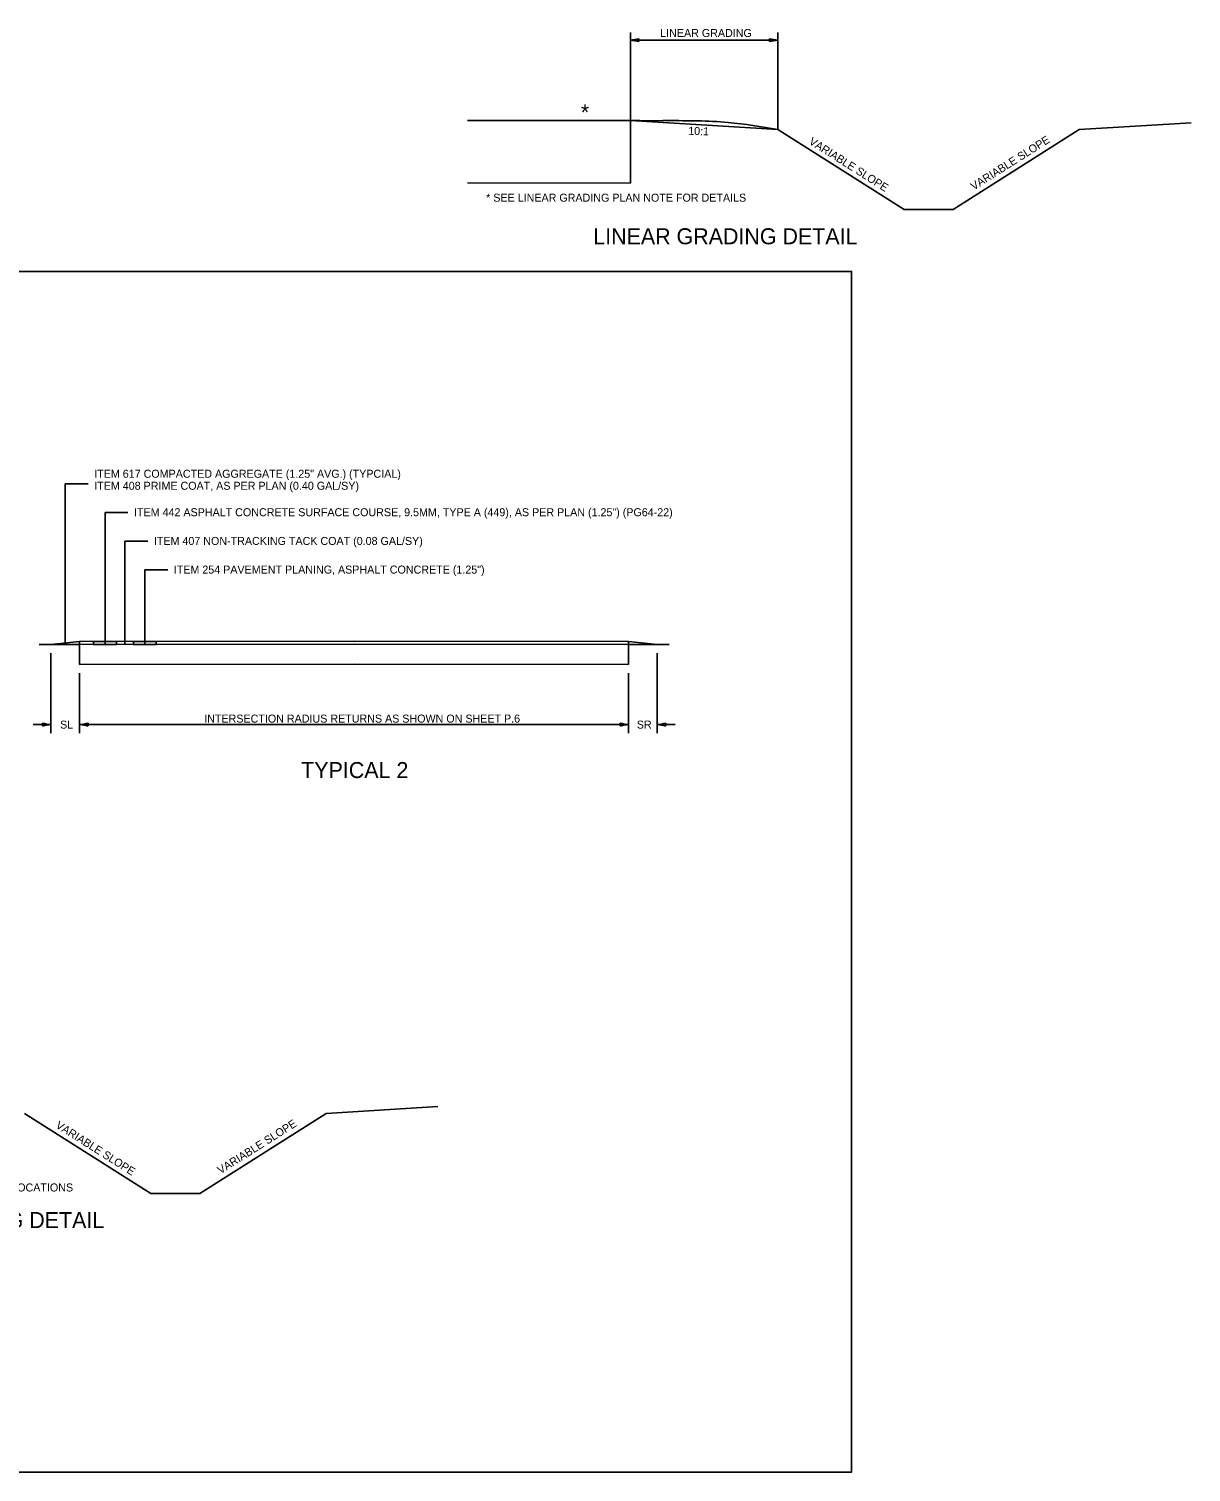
# Model space of a CAD drawing. Extents: x 12069 to 12219, y 28137 to 28231.
# Drawn here: x 12085.56 to 12105.88, y 28179.53 to 28204.77 of the extents above; entities that cross this region are included whole.
import ezdxf

# ---------------------------------------------------------------- set-up
doc = ezdxf.new("R2010")
doc.units = 0
doc.layers.add('SC_Scratch1', color=7, linetype='Continuous')
doc.layers.add('SH_Data', color=7, linetype='Continuous')

msp = doc.modelspace()

# ---------------------------------------------------------------- linework, layer by layer
at = {"layer": 'SC_Scratch1'}
msp.add_lwpolyline([(12069.445, 28200.534), (12099.945, 28200.534), (12099.945, 28179.534), (12069.445, 28179.534)], close=True, dxfattribs=at)
at = {"layer": 'SH_Data'}
for p, q in [((12096.078, 28203.247), (12096.078, 28204.711)), ((12096.078, 28204.577), (12098.656, 28204.577)), ((12096.219, 28204.577), (12096.228, 28204.602)), ((12096.228, 28204.552), (12096.219, 28204.577)), ((12098.506, 28204.602), (12098.515, 28204.577)), ((12098.515, 28204.577), (12098.506, 28204.552)), ((12098.656, 28203.012), (12098.656, 28204.711)), ((12096.078, 28203.169), (12096.078, 28203.325)), ((12093.231, 28203.173), (12096.078, 28203.169)), ((12098.656, 28203.012), (12096.078, 28203.169)), ((12096.078, 28202.075), (12096.078, 28203.169)), ((12103.927, 28203.012), (12105.882, 28203.132)), ((12098.656, 28203.012), (12100.864, 28201.614)), ((12103.927, 28203.012), (12101.719, 28201.614)), ((12093.229, 28202.079), (12096.078, 28202.075)), ((12100.864, 28201.614), (12101.719, 28201.614)), ((12086.197, 28194.033), (12086.197, 28196.819)), ((12086.197, 28196.819), (12086.597, 28196.819)), ((12086.892, 28194.008), (12086.892, 28196.318)), ((12086.892, 28196.318), (12087.292, 28196.318)), ((12087.24, 28194.009), (12087.24, 28195.817)), ((12087.24, 28195.817), (12087.64, 28195.817)), ((12087.588, 28194.009), (12087.588, 28195.315)), ((12087.588, 28195.315), (12087.988, 28195.315)), ((12086.447, 28194.008), (12085.739, 28194.008)), ((12085.947, 28194.008), (12086.447, 28194.058)), ((12091.247, 28194.065), (12086.447, 28194.058)), ((12086.447, 28194.008), (12086.447, 28194.058)), ((12091.247, 28194.015), (12086.447, 28194.008)), ((12086.447, 28193.958), (12086.447, 28194.008)), ((12086.692, 28194.058), (12087.092, 28194.059)), ((12086.692, 28194.008), (12086.692, 28194.058)), ((12087.092, 28194.009), (12086.692, 28194.008)), ((12087.092, 28194.059), (12087.092, 28194.009)), ((12087.388, 28194.059), (12087.788, 28194.06)), ((12087.388, 28194.009), (12087.388, 28194.059)), ((12087.788, 28194.01), (12087.388, 28194.009)), ((12087.788, 28194.06), (12087.788, 28194.01)), ((12091.247, 28194.065), (12096.047, 28194.058)), ((12091.247, 28194.015), (12096.047, 28194.008)), ((12096.047, 28194.008), (12096.047, 28194.058)), ((12096.547, 28194.008), (12096.047, 28194.058)), ((12096.047, 28193.958), (12096.047, 28194.008)), ((12096.047, 28194.008), (12096.755, 28194.008)), ((12085.947, 28193.858), (12085.947, 28192.458)), ((12086.447, 28193.658), (12086.447, 28193.958)), ((12096.047, 28193.658), (12096.047, 28193.958)), ((12096.547, 28193.858), (12096.547, 28192.458)), ((12091.247, 28193.665), (12086.447, 28193.658)), ((12086.447, 28193.508), (12086.447, 28192.458)), ((12091.247, 28193.665), (12096.047, 28193.658)), ((12096.047, 28193.508), (12096.047, 28192.458)), ((12085.947, 28192.608), (12085.634, 28192.608)), ((12085.797, 28192.633), (12085.805, 28192.608)), ((12085.805, 28192.608), (12085.797, 28192.583)), ((12086.447, 28192.608), (12096.047, 28192.608)), ((12086.589, 28192.608), (12086.597, 28192.633)), ((12086.597, 28192.583), (12086.589, 28192.608)), ((12095.897, 28192.633), (12095.905, 28192.608)), ((12095.905, 28192.608), (12095.897, 28192.583)), ((12096.547, 28192.608), (12096.86, 28192.608)), ((12096.697, 28192.633), (12096.689, 28192.608)), ((12096.689, 28192.608), (12096.697, 28192.583)), ((12090.757, 28185.807), (12092.712, 28185.927)), ((12085.486, 28185.807), (12087.694, 28184.409)), ((12090.757, 28185.807), (12088.549, 28184.409)), ((12087.694, 28184.409), (12088.549, 28184.409))]:
    msp.add_line(p, q, dxfattribs=at)
for centre, start, end in [((12096.038, 28205.281), 273.2737, 285.6509), ((12096.038, 28203.872), 74.3491, 86.7263), ((12098.697, 28205.281), 254.3491, 266.7263), ((12098.697, 28203.872), 93.2737, 105.6509), ((12085.987, 28193.312), 254.3491, 266.7263), ((12085.987, 28191.903), 93.2737, 105.6509), ((12086.407, 28193.312), 273.2737, 285.6509), ((12086.407, 28191.903), 74.3491, 86.7263), ((12096.087, 28193.312), 254.3491, 266.7263), ((12096.087, 28191.903), 93.2737, 105.6509), ((12096.507, 28193.312), 273.2737, 285.6509), ((12096.507, 28191.903), 74.3491, 86.7263)]:
    msp.add_arc(centre, 0.705, start, end, dxfattribs=at)
msp.add_spline([(12096.078, 28203.169), (12096.728, 28203.169), (12097.785, 28203.138), (12098.656, 28203.012)], degree=3, dxfattribs=at)

# ---------------------------------------------------------------- texts
for s, height, p in [('LINEAR GRADING', 0.14, (12096.599, 28204.632)), ('*', 0.28, (12095.211, 28203.175)), ('* SEE LINEAR GRADING PLAN NOTE FOR DETAILS', 0.14, (12093.556, 28201.752)), ('LINEAR GRADING DETAIL', 0.28, (12095.429, 28201.007)), ('ITEM 617 COMPACTED AGGREGATE (1.25" AVG.) (TYPCIAL)', 0.14, (12086.703, 28196.924)), ('ITEM 408 PRIME COAT, AS PER PLAN (0.40 GAL/SY)', 0.14, (12086.703, 28196.714)), ('ITEM 442 ASPHALT CONCRETE SURFACE COURSE, 9.5MM, TYPE A (449), AS PER PLAN (1.25") (PG64-22)', 0.14, (12087.399, 28196.251)), ('ITEM 407 NON-TRACKING TACK COAT (0.08 GAL/SY)', 0.14, (12087.746, 28195.749)), ('ITEM 254 PAVEMENT PLANING, ASPHALT CONCRETE (1.25")', 0.14, (12088.094, 28195.248)), ('INTERSECTION RADIUS RETURNS AS SHOWN ON SHEET P.6', 0.14, (12088.626, 28192.642)), ('SL', 0.14, (12086.106, 28192.537)), ('SR', 0.14, (12096.19, 28192.537)), ('TYPICAL 2', 0.28, (12090.322, 28191.672)), ('     SEE PAVEMENT AND SHOULDER DATA SHEET FOR LOCATIONS', 0.14, (12080.269, 28184.442)), ('LINEAR GRADING DETAIL', 0.28, (12082.259, 28183.802))]:
    msp.add_text(s, height=height, dxfattribs=at).set_placement(p)
for s, rotation, p in [('10:1', 358.09, (12097.087, 28202.923)), ('VARIABLE SLOPE', 327.6541, (12099.187, 28202.771)), ('VARIABLE SLOPE', 32.3459, (12102.081, 28201.946)), ('VARIABLE SLOPE', 327.6541, (12086.017, 28185.566)), ('VARIABLE SLOPE', 32.3459, (12088.911, 28184.741))]:
    msp.add_text(s, height=0.14, rotation=rotation, dxfattribs=at).set_placement(p)

doc.saveas('drawing.dxf')
